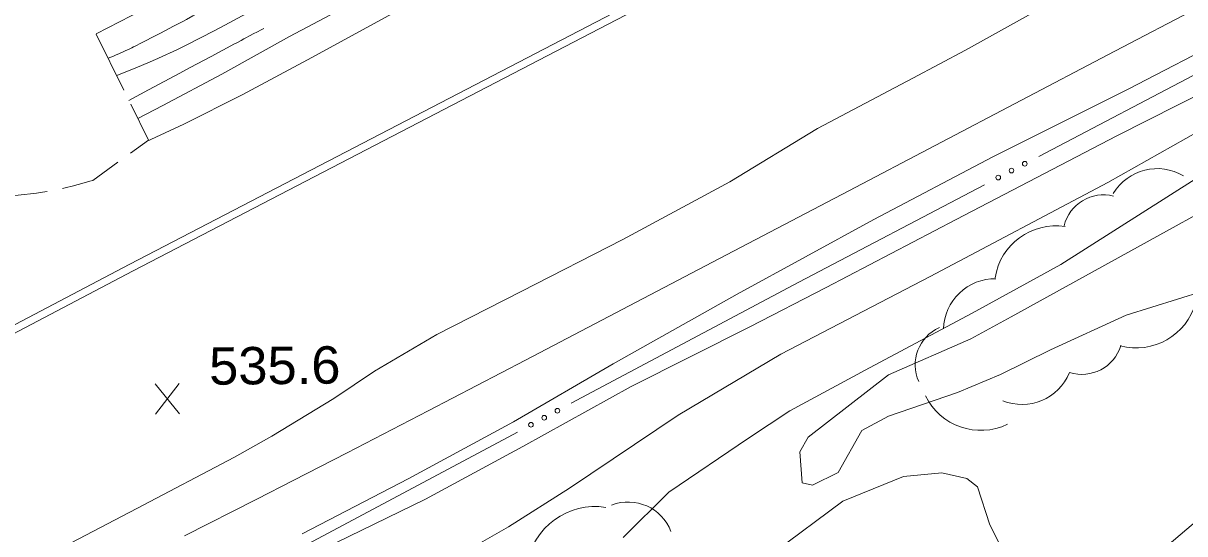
# Model space of a CAD drawing. Extents: x 2361284 to 2366480, y 6976556 to 6985346.
# Drawn here: x 2361781.9 to 2361931, y 6977542.1 to 6977607.7 of the extents above; entities that cross this region are included whole.
import ezdxf

# ---------------------------------------------------------------- set-up
doc = ezdxf.new("R2010")
doc.units = 0
doc.header["$LTSCALE"] = 1.9
for name, color, linetype, lineweight in [('12', 7, 'Continuous', 13), ('13', 7, 'Continuous', 13), ('16', 7, 'Continuous', 13), ('21', 7, 'Continuous', 13), ('24', 7, 'Continuous', 13), ('3', 7, 'Continuous', 13)]:
    doc.layers.add(name, color=color, linetype=linetype, lineweight=lineweight)

msp = doc.modelspace()

# ---------------------------------------------------------------- linework, layer by layer
at = {"layer": '12'}
for p, q in [((2361801.997, 6977557.538), (2361798.88, 6977561.389)), ((2361798.917, 6977557.509), (2361801.96, 6977561.418))]:
    msp.add_line(p, q, dxfattribs=at)
for points in [[(2361781.56, 6977537.57), (2361796.496, 6977545.364), (2361809.025, 6977551.952), (2361813.819, 6977554.648), (2361821.804, 6977559.494), (2361827.02, 6977563.014), (2361834.996, 6977567.731), (2361845.854, 6977573.234), (2361858.871, 6977579.887), (2361872.612, 6977587.318), (2361883.877, 6977594.137), (2361896.097, 6977600.593), (2361902.852, 6977604.188), (2361914.403, 6977610.618), (2361925.336, 6977616.662), (2361930.926, 6977619.795), (2361937.688, 6977623.83), (2361950.207, 6977631.319), (2361964.755, 6977640.048), (2361969.596, 6977643.174), (2361977.636, 6977648.591), (2361984.579, 6977653.387), (2361992.135, 6977658.07), (2361995.227, 6977659.959)], [(2361987.704, 6977621.395), (2361986.957, 6977620.998), (2361960.127, 6977607.271), (2361932.813, 6977593.802), (2361921.135, 6977587.23), (2361898.319, 6977575.143), (2361879.152, 6977565.179), (2361865.967, 6977557.374), (2361852.034, 6977547.992), (2361844.222, 6977543.046), (2361832.843, 6977536.518), (2361827.127, 6977532.883), (2361820.194, 6977528.957), (2361816.005, 6977524.607), (2361813.165, 6977522.54), (2361808.714, 6977519.428), (2361804.64, 6977515.599)], [(2361812.494, 6977609.909), (2361811.161, 6977609.195), (2361808.375, 6977607.717), (2361806.511, 6977606.743), (2361802.772, 6977604.815), (2361801.812, 6977604.335), (2361801.168, 6977604.025), (2361799.87, 6977603.424), (2361799.218, 6977603.132), (2361797.905, 6977602.564), (2361796.584, 6977602.012), (2361793.927, 6977600.942)]]:
    msp.add_lwpolyline(points, dxfattribs=at)
at = {"layer": '13'}
for points in [[(2362130.199, 6977800.54), (2362116.102, 6977792.726), (2362105.414, 6977786.133), (2362073.113, 6977767.126), (2362053.314, 6977754.316), (2362028.391, 6977740.808), (2361999.405, 6977724.482), (2361976.744, 6977710.776), (2361953.89, 6977697.427), (2361930.643, 6977684.236), (2361890.841, 6977660.077), (2361869.963, 6977648.187), (2361846.997, 6977635.988), (2361826.513, 6977624.783), (2361814.165, 6977618.205), (2361801.776, 6977611.737), (2361791.296, 6977606.286)], [(2362126.862, 6977783.276), (2362114.007, 6977775.364), (2362101.992, 6977768.39), (2362087.267, 6977759.489), (2362074.585, 6977751.088), (2362056.201, 6977740.913), (2362041.783, 6977731.185), (2362025.889, 6977722.104), (2362012.321, 6977713.304), (2361996.486, 6977704.253), (2361979.481, 6977694.3), (2361957.113, 6977681.298), (2361941.84, 6977673.131), (2361923.219, 6977661.524), (2361908.09, 6977651.82), (2361891.676, 6977642.813), (2361879.855, 6977636.37), (2361863.592, 6977627.165), (2361847.314, 6977618.5), (2361836.387, 6977612.806), (2361818.429, 6977602.945), (2361810.042, 6977598.475), (2361802.558, 6977594.694), (2361797.769, 6977592.488)], [(2362119.865, 6977692.575), (2362112.657, 6977689.097), (2362098.821, 6977682.205), (2362090.151, 6977678.063), (2362079.671, 6977672.642), (2362061.64, 6977664.31), (2362050.983, 6977658.719), (2362036.047, 6977650.856), (2362026.017, 6977645.56), (2362011.43, 6977637.721), (2361997.335, 6977630.817), (2361977.069, 6977620.904), (2361957.681, 6977610.979), (2361941.845, 6977603.108), (2361922.289, 6977593.212), (2361901.639, 6977582.464), (2361884.991, 6977573.756), (2361875.159, 6977568.683), (2361859.961, 6977561.037), (2361846.053, 6977553.324), (2361833.547, 6977546.596), (2361822.069, 6977540.996)], [(2361858.905, 6977541.676), (2361864.771, 6977547.473), (2361875.014, 6977554.43), (2361880.301, 6977557.91), (2361890.53, 6977563.428), (2361903.733, 6977570.454), (2361915.105, 6977576.703), (2361935.96, 6977589.962), (2361950.798, 6977597.623), (2361968.638, 6977607.192), (2361993.633, 6977620.441), (2362008.978, 6977628.488), (2362021.094, 6977635.333), (2362034.683, 6977642.843), (2362042.373, 6977647.046), (2362053.626, 6977653.073), (2362062.184, 6977657.586), (2362081.524, 6977667.169), (2362093.152, 6977671.74), (2362103.136, 6977676.466), (2362112.248, 6977680.603), (2362118.733, 6977683.305), (2362132.169, 6977689.073)], [(2361935.164, 6977673.678), (2361922.32, 6977665.585), (2361911.135, 6977658.69), (2361895.925, 6977650.234), (2361883.73, 6977643.238), (2361867.573, 6977633.463), (2361853.704, 6977625.891), (2361842.362, 6977619.813), (2361830.271, 6977613.498), (2361816.112, 6977605.962), (2361807.427, 6977601.11), (2361799.865, 6977597.088), (2361796.63, 6977595.447)], [(2361817.728, 6977542.114), (2361831.312, 6977549.184), (2361844.864, 6977556.513), (2361857.623, 6977563.935), (2361873.538, 6977572.907), (2361891.099, 6977582.494), (2361906.383, 6977590.501), (2361923.712, 6977599.206), (2361936.778, 6977605.969), (2361948.926, 6977612.546), (2361963.349, 6977620.693), (2361972.591, 6977625.762), (2361983.952, 6977632.121), (2362005.696, 6977643.457)], [(2361810.173, 6977612.047), (2361808.021, 6977610.894), (2361803.716, 6977608.594), (2361802.887, 6977608.152), (2361802.334, 6977607.859), (2361801.226, 6977607.275), (2361800.672, 6977606.984), (2361799.562, 6977606.405), (2361798.45, 6977605.829), (2361797.708, 6977605.446), (2361797.213, 6977605.191), (2361796.222, 6977604.683), (2361796.099, 6977604.621), (2361795.853, 6977604.498), (2361795.606, 6977604.378), (2361795.44, 6977604.299), (2361795.108, 6977604.144), (2361794.858, 6977604.03), (2361794.691, 6977603.955), (2361794.355, 6977603.807), (2361794.187, 6977603.734), (2361793.85, 6977603.589), (2361793.513, 6977603.446), (2361792.836, 6977603.161)], [(2361812.792, 6977606.99), (2361812.654, 6977606.916), (2361812.469, 6977606.818), (2361812.377, 6977606.769), (2361812.099, 6977606.622), (2361811.915, 6977606.524), (2361811.545, 6977606.328), (2361810.99, 6977606.034), (2361810.497, 6977605.773), (2361810.251, 6977605.643), (2361809.881, 6977605.447), (2361809.512, 6977605.251), (2361809.327, 6977605.153), (2361809.05, 6977605.005), (2361806.038, 6977603.397), (2361803.361, 6977601.968), (2361802.022, 6977601.253), (2361800.015, 6977600.181), (2361798.007, 6977599.108), (2361797.003, 6977598.572), (2361795.498, 6977597.767)], [(2361933.358, 6977573.286), (2361923.457, 6977570.192), (2361913.769, 6977565.74), (2361907.368, 6977562.578), (2361901.81, 6977560.285), (2361892.989, 6977557.251), (2361889.567, 6977555.388), (2361886.528, 6977549.989), (2361883.242, 6977548.4), (2361881.899, 6977548.676), (2361881.615, 6977552.664), (2361882.673, 6977554.552), (2361892.979, 6977562.521), (2361903.554, 6977567.163), (2361908.739, 6977570.002), (2361928.635, 6977580.981), (2361942.145, 6977588.4)], [(2361908.234, 6977538.795), (2361905.961, 6977543.304), (2361904.405, 6977548.15), (2361903.041, 6977549.246), (2361899.819, 6977549.965), (2361894.893, 6977549.508), (2361887.103, 6977546.315), (2361878.274, 6977539.72)], [(2361928.71, 6977540.55), (2361934.374, 6977545.375)]]:
    msp.add_lwpolyline(points, dxfattribs=at)
at = {"layer": '16'}
for centre, radius, start, end in [((2361927.453, 6977582.436), 6.569, 58.98305, 148.98305), ((2361920.601, 6977580.391), 5.25, 76.11666, 166.11666), ((2361914.441, 6977573.782), 7.88, 81.23761, 171.23761), ((2361906.61, 6977568.29), 6.569, 88.71736, 178.71736), ((2361924.788, 6977573.877), 7.88, 254.81189, 344.81189), ((2361901.651, 6977563.818), 5.25, 114.17763, 204.17763), ((2361917.784, 6977567.85), 5.25, 252.64101, 342.64101), ((2361910.108, 6977565.302), 6.569, 247.83968, 337.83968), ((2361904.813, 6977563.293), 7.88, 205.82605, 295.82605), ((2361855.325, 6977536.802), 8.835, 81.10766, 171.10766), ((2361859.566, 6977540.327), 5.886, 21.10499, 111.10499)]:
    msp.add_arc(centre, radius, start, end, dxfattribs=at)
at = {"layer": '21'}
for points in [[(2361965.421, 6977618.373), (2361933.787, 6977601.852), (2361912.253, 6977590.576)], [(2361905.306, 6977586.939), (2361881.464, 6977574.453), (2361852.271, 6977558.884)], [(2361845.355, 6977555.198), (2361837.734, 6977551.135), (2361794.013, 6977527.798), (2361792.4, 6977526.983)]]:
    msp.add_lwpolyline(points, dxfattribs=at)
for centre in [(2361908.761, 6977588.746), (2361910.462, 6977589.636), (2361907.06, 6977587.855), (2361848.79, 6977557.032), (2361850.485, 6977557.935), (2361847.096, 6977556.129)]:
    msp.add_circle(centre, 0.3, dxfattribs=at)
at = {"layer": '24'}
msp.add_line((2361794.845, 6977599.08), (2361791.307, 6977606.256), dxfattribs=at)
for points in [[(2361795.702, 6977590.998), (2361798.007, 6977592.66), (2361795.732, 6977597.289)], [(2361786.976, 6977586.464), (2361787.475, 6977586.569), (2361788.233, 6977586.746), (2361788.99, 6977586.953), (2361789.748, 6977587.16), (2361790.496, 6977587.378), (2361790.865, 6977587.492), (2361794.083, 6977589.823)], [(2361777.045, 6977585.44), (2361777.385, 6977585.433), (2361778.165, 6977585.44), (2361778.945, 6977585.458), (2361779.724, 6977585.495), (2361780.514, 6977585.543), (2361781.294, 6977585.6), (2361782.073, 6977585.677), (2361782.852, 6977585.765), (2361783.621, 6977585.862), (2361784.4, 6977585.98), (2361785.009, 6977586.075)]]:
    msp.add_lwpolyline(points, dxfattribs=at)
at = {"layer": '3'}
for points in [[(2361749.171, 6977552.323), (2361749.138, 6977552.303), (2361795.597, 6977576.746), (2362013.891, 6977690.167), (2362206.999, 6977790.39), (2362401.822, 6977891.177)], [(2361749.586, 6977551.457), (2361749.586, 6977551.457), (2361796.045, 6977575.901), (2362014.329, 6977689.312), (2362207.437, 6977789.534), (2362402.259, 6977890.321)], [(2362128.101, 6977711.529), (2362096.61, 6977695.131), (2362033.599, 6977662.389), (2362002.101, 6977646.003), (2361983.397, 6977636.245), (2361970.935, 6977629.728), (2361946.02, 6977616.672), (2361921.114, 6977603.6), (2361887.906, 6977586.17), (2361871.297, 6977577.465), (2361846.37, 6977564.431), (2361833.899, 6977557.929), (2361830.435, 6977556.128), (2361823.5, 6977552.541), (2361816.556, 6977548.971), (2361811.922, 6977546.601), (2361802.644, 6977541.879)]]:
    msp.add_lwpolyline(points, dxfattribs=at)

# ---------------------------------------------------------------- texts
at = {"layer": '12', "width": 1.05}
msp.add_text('535.6', height=4.799, rotation=0.545, dxfattribs=at).set_placement((2361805.806, 6977561.262))

doc.saveas('drawing.dxf')
